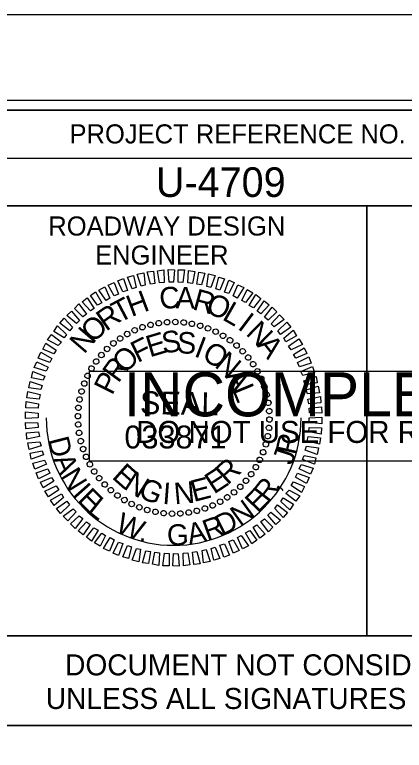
# Model space of a CAD drawing. Extents: x 1779926 to 1781626, y 618464 to 619564.
# Drawn here: x 1781400.8 to 1781502.8, y 619371.7 to 619564.2 of the extents above; entities that cross this region are included whole.
import ezdxf

# ---------------------------------------------------------------- set-up
doc = ezdxf.new("R2010")
doc.units = 0
for name, color, linetype in [('Old_Level_58', 7, 'Continuous'), ('Scratch_Level_0', 7, 'Continuous'), ('Sheet Data Field CELL', 7, 'Continuous'), ('Sheet Plot Border Inside CELL', 7, 'Continuous'), ('Sheet Plot Border Outside CELL', 7, 'Continuous'), ('Sheet Professional Seal CELL', 7, 'Continuous'), ('Sheet Profile CELL', 7, 'Continuous'), ('Sheet Profile Grid Major CELL', 7, 'Continuous'), ('Sheet Profile Grid Minor CELL', 7, 'Continuous'), ('Sheet Sticker Exception Certification CELL', 7, 'Continuous'), ('Sheet Sticker Incomplete CELL', 7, 'Continuous')]:
    doc.layers.add(name, color=color, linetype=linetype)

msp = doc.modelspace()

# ---------------------------------------------------------------- linework, layer by layer
at = {"layer": 'Old_Level_58'}
for points in [[(1781392.9, 619378.14), (1781592.96, 619378.14), (1781592.96, 619314.19), (1781392.9, 619314.19)], [(1781392.96, 619378.14), (1781592.96, 619378.14), (1781592.96, 619314.19), (1781392.96, 619314.19)]]:
    msp.add_lwpolyline(points, close=True, dxfattribs=at)
at = {"layer": 'Scratch_Level_0'}
msp.add_arc((1781442.39, 619458.69), 33.36, 180, 360, dxfattribs=at)
at = {"layer": 'Sheet Plot Border Inside CELL'}
msp.add_lwpolyline([(1779938.96, 618486.64), (1781605.46, 618486.64), (1781605.46, 619541.74), (1779938.96, 619541.74)], close=True, dxfattribs=at)
at = {"layer": 'Sheet Plot Border Outside CELL'}
msp.add_lwpolyline([(1779925.96, 618464.19), (1781625.96, 618464.19), (1781625.96, 619564.19), (1779925.96, 619564.19)], close=True, dxfattribs=at)
at = {"layer": 'Sheet Professional Seal CELL'}
for p, q in [((1781434.19, 619482.44), (1781434.19, 619482.44)), ((1781436.29, 619483.04), (1781436.29, 619483.04)), ((1781438.49, 619483.44), (1781438.49, 619483.44)), ((1781440.64, 619483.74), (1781440.64, 619483.74)), ((1781442.84, 619483.79), (1781442.84, 619483.79)), ((1781445.04, 619483.64), (1781445.04, 619483.64)), ((1781447.19, 619483.29), (1781447.19, 619483.29)), ((1781449.29, 619482.84), (1781449.29, 619482.84)), ((1781430.24, 619480.64), (1781430.24, 619480.64)), ((1781432.19, 619481.64), (1781432.19, 619481.64)), ((1781451.39, 619482.14), (1781451.39, 619482.14)), ((1781453.39, 619481.24), (1781453.39, 619481.24)), ((1781428.34, 619479.49), (1781428.34, 619479.49)), ((1781455.34, 619480.24), (1781455.34, 619480.24)), ((1781457.14, 619478.99), (1781457.14, 619478.99)), ((1781424.94, 619476.74), (1781424.94, 619476.74)), ((1781426.59, 619478.24), (1781426.59, 619478.24)), ((1781458.89, 619477.64), (1781458.89, 619477.64)), ((1781423.44, 619475.19), (1781423.44, 619475.19)), ((1781460.44, 619476.14), (1781460.44, 619476.14)), ((1781422.09, 619473.44), (1781422.09, 619473.44)), ((1781461.94, 619474.49), (1781461.94, 619474.49)), ((1781463.19, 619472.74), (1781463.19, 619472.74)), ((1781420.84, 619471.64), (1781420.84, 619471.64)), ((1781464.34, 619470.84), (1781464.34, 619470.84)), ((1781419.84, 619469.69), (1781419.84, 619469.69)), ((1781465.34, 619468.89), (1781465.34, 619468.89)), ((1781418.94, 619467.69), (1781418.94, 619467.69)), ((1781418.24, 619465.59), (1781418.24, 619465.59)), ((1781466.14, 619466.89), (1781466.14, 619466.89)), ((1781417.79, 619463.49), (1781417.79, 619463.49)), ((1781466.74, 619464.79), (1781466.74, 619464.79)), ((1781417.44, 619461.34), (1781417.44, 619461.34)), ((1781467.14, 619462.59), (1781467.14, 619462.59)), ((1781467.44, 619460.44), (1781467.44, 619460.44)), ((1781417.29, 619459.14), (1781417.29, 619459.14)), ((1781442.39, 619458.69), (1781442.39, 619458.69)), ((1781467.49, 619458.24), (1781467.49, 619458.24)), ((1781417.34, 619456.94), (1781417.34, 619456.94)), ((1781467.34, 619456.04), (1781467.34, 619456.04)), ((1781417.64, 619454.79), (1781417.64, 619454.79)), ((1781466.99, 619453.89), (1781466.99, 619453.89)), ((1781418.04, 619452.59), (1781418.04, 619452.59)), ((1781466.54, 619451.79), (1781466.54, 619451.79)), ((1781418.64, 619450.49), (1781418.64, 619450.49)), ((1781465.84, 619449.69), (1781465.84, 619449.69)), ((1781419.44, 619448.49), (1781419.44, 619448.49)), ((1781464.94, 619447.69), (1781464.94, 619447.69)), ((1781420.44, 619446.54), (1781420.44, 619446.54)), ((1781421.59, 619444.64), (1781421.59, 619444.64)), ((1781462.69, 619443.94), (1781462.69, 619443.94)), ((1781463.94, 619445.74), (1781463.94, 619445.74)), ((1781422.84, 619442.89), (1781422.84, 619442.89)), ((1781461.34, 619442.19), (1781461.34, 619442.19)), ((1781424.34, 619441.24), (1781424.34, 619441.24)), ((1781459.84, 619440.64), (1781459.84, 619440.64)), ((1781425.89, 619439.74), (1781425.89, 619439.74)), ((1781427.64, 619438.39), (1781427.64, 619438.39)), ((1781458.19, 619439.14), (1781458.19, 619439.14)), ((1781429.44, 619437.14), (1781429.44, 619437.14)), ((1781431.39, 619436.14), (1781431.39, 619436.14)), ((1781454.54, 619436.74), (1781454.54, 619436.74)), ((1781456.44, 619437.89), (1781456.44, 619437.89)), ((1781433.39, 619435.24), (1781433.39, 619435.24)), ((1781435.49, 619434.54), (1781435.49, 619434.54)), ((1781448.49, 619434.34), (1781448.49, 619434.34)), ((1781450.59, 619434.94), (1781450.59, 619434.94)), ((1781452.59, 619435.74), (1781452.59, 619435.74)), ((1781437.59, 619434.09), (1781437.59, 619434.09)), ((1781439.74, 619433.74), (1781439.74, 619433.74)), ((1781441.94, 619433.59), (1781441.94, 619433.59)), ((1781444.14, 619433.64), (1781444.14, 619433.64)), ((1781446.29, 619433.94), (1781446.29, 619433.94))]:
    msp.add_line(p, q, dxfattribs=at)
for points in [[(1781431.49, 619492.49), (1781430.34, 619495.49), (1781431.89, 619495.94), (1781432.54, 619492.84)], [(1781433.89, 619493.14), (1781432.84, 619496.29), (1781434.54, 619496.64), (1781434.94, 619493.39)], [(1781436.29, 619493.69), (1781435.49, 619496.89), (1781437.14, 619497.04), (1781437.49, 619493.84)], [(1781438.69, 619493.99), (1781438.14, 619497.19), (1781439.84, 619497.39), (1781439.89, 619494.14)], [(1781441.19, 619494.24), (1781440.94, 619497.49), (1781442.59, 619497.44), (1781442.39, 619494.19)], [(1781443.59, 619494.19), (1781443.59, 619497.44), (1781445.24, 619497.39), (1781444.79, 619494.14)], [(1781446.09, 619494.04), (1781446.29, 619497.29), (1781447.94, 619496.99), (1781447.29, 619493.84)], [(1781448.49, 619493.64), (1781448.94, 619496.84), (1781450.59, 619496.59), (1781449.69, 619493.49)], [(1781451.04, 619493.09), (1781451.54, 619496.34), (1781453.24, 619495.94), (1781452.09, 619492.84)], [(1781426.84, 619490.64), (1781425.24, 619493.44), (1781426.79, 619494.14), (1781427.94, 619491.09)], [(1781429.04, 619491.69), (1781427.74, 619494.59), (1781429.24, 619495.19), (1781430.29, 619491.99)], [(1781453.44, 619492.44), (1781454.19, 619495.54), (1781455.74, 619495.04), (1781454.49, 619492.09)], [(1781455.69, 619491.54), (1781456.84, 619494.69), (1781458.24, 619494.09), (1781456.84, 619491.19)], [(1781424.69, 619489.44), (1781422.84, 619492.14), (1781424.39, 619492.94), (1781425.64, 619490.04)], [(1781457.94, 619490.59), (1781459.19, 619493.54), (1781460.74, 619492.84), (1781459.04, 619490.04)], [(1781460.24, 619489.44), (1781461.59, 619492.29), (1781463.09, 619491.44), (1781461.19, 619488.84)], [(1781420.59, 619486.69), (1781418.44, 619489.09), (1781419.79, 619490.14), (1781421.54, 619487.34)], [(1781422.49, 619488.19), (1781420.64, 619490.74), (1781421.94, 619491.69), (1781423.59, 619488.79)], [(1781462.19, 619488.09), (1781463.94, 619490.99), (1781465.24, 619489.94), (1781463.29, 619487.49)], [(1781418.59, 619485.14), (1781416.39, 619487.34), (1781417.59, 619488.54), (1781419.54, 619485.84)], [(1781464.24, 619486.59), (1781466.09, 619489.34), (1781467.39, 619488.24), (1781465.19, 619485.89)], [(1781416.94, 619483.39), (1781414.39, 619485.44), (1781415.64, 619486.59), (1781417.74, 619484.19)], [(1781466.14, 619485.04), (1781468.19, 619487.64), (1781469.39, 619486.44), (1781467.09, 619484.29)], [(1781415.19, 619481.49), (1781412.59, 619483.44), (1781413.69, 619484.74), (1781415.89, 619482.39)], [(1781467.94, 619483.29), (1781470.09, 619485.64), (1781471.29, 619484.44), (1781468.69, 619482.49)], [(1781413.69, 619479.59), (1781410.99, 619481.29), (1781411.94, 619482.74), (1781414.34, 619480.54)], [(1781469.69, 619481.49), (1781471.99, 619483.74), (1781473.04, 619482.39), (1781470.39, 619480.49)], [(1781412.19, 619477.59), (1781409.39, 619479.09), (1781410.39, 619480.49), (1781412.99, 619478.49)], [(1781471.19, 619479.54), (1781473.64, 619481.64), (1781474.59, 619480.19), (1781471.79, 619478.59)], [(1781472.49, 619477.49), (1781475.14, 619479.39), (1781476.09, 619477.89), (1781473.19, 619476.49)], [(1781410.99, 619475.44), (1781408.14, 619476.69), (1781408.89, 619478.24), (1781411.59, 619476.39)], [(1781473.79, 619475.29), (1781476.59, 619477.04), (1781477.24, 619475.49), (1781474.39, 619474.34)], [(1781409.99, 619473.14), (1781406.89, 619474.29), (1781407.64, 619475.84), (1781410.49, 619474.24)], [(1781474.79, 619473.14), (1781477.74, 619474.64), (1781478.39, 619473.04), (1781475.29, 619472.04)], [(1781408.99, 619470.94), (1781405.89, 619471.84), (1781406.54, 619473.39), (1781409.54, 619471.99)], [(1781408.24, 619468.54), (1781405.14, 619469.19), (1781405.49, 619470.84), (1781408.64, 619469.59)], [(1781475.69, 619470.79), (1781478.74, 619472.09), (1781479.29, 619470.54), (1781476.19, 619469.74)], [(1781476.49, 619468.39), (1781479.69, 619469.54), (1781479.99, 619467.89), (1781476.84, 619467.34)], [(1781407.59, 619466.14), (1781404.49, 619466.54), (1781404.84, 619468.24), (1781407.99, 619467.19)], [(1781477.09, 619465.99), (1781480.24, 619466.94), (1781480.54, 619465.24), (1781477.39, 619464.94)], [(1781407.19, 619463.59), (1781403.99, 619463.89), (1781404.19, 619465.59), (1781407.44, 619464.79)], [(1781477.54, 619463.59), (1781480.79, 619464.29), (1781480.94, 619462.59), (1781477.74, 619462.39)], [(1781406.94, 619461.19), (1781403.69, 619461.29), (1781403.79, 619462.94), (1781407.04, 619462.39)], [(1781477.84, 619461.19), (1781481.09, 619461.59), (1781481.19, 619459.89), (1781477.94, 619459.99)], [(1781406.89, 619458.69), (1781403.64, 619458.54), (1781403.64, 619460.24), (1781406.89, 619459.89)], [(1781406.94, 619456.19), (1781403.69, 619455.79), (1781403.59, 619457.49), (1781406.84, 619457.39)], [(1781477.89, 619458.69), (1781481.14, 619458.84), (1781481.14, 619457.14), (1781477.89, 619457.49)], [(1781477.84, 619456.19), (1781481.09, 619456.09), (1781480.99, 619454.44), (1781477.74, 619454.99)], [(1781407.24, 619453.79), (1781403.99, 619453.09), (1781403.84, 619454.79), (1781407.04, 619454.99)], [(1781477.59, 619453.79), (1781480.79, 619453.49), (1781480.59, 619451.79), (1781477.34, 619452.59)], [(1781407.69, 619451.39), (1781404.54, 619450.44), (1781404.24, 619452.14), (1781407.39, 619452.44)], [(1781408.29, 619448.99), (1781405.09, 619447.84), (1781404.79, 619449.49), (1781407.94, 619450.04)], [(1781477.19, 619451.24), (1781480.29, 619450.84), (1781479.94, 619449.14), (1781476.79, 619450.19)], [(1781476.54, 619448.84), (1781479.64, 619448.19), (1781479.29, 619446.54), (1781476.14, 619447.79)], [(1781409.09, 619446.59), (1781406.04, 619445.29), (1781405.49, 619446.84), (1781408.59, 619447.64)], [(1781475.79, 619446.44), (1781478.89, 619445.54), (1781478.24, 619443.99), (1781475.24, 619445.39)], [(1781409.99, 619444.24), (1781407.04, 619442.74), (1781406.39, 619444.34), (1781409.49, 619445.34)], [(1781474.79, 619444.24), (1781477.89, 619443.09), (1781477.14, 619441.54), (1781474.29, 619443.14)], [(1781410.99, 619442.09), (1781408.19, 619440.34), (1781407.54, 619441.89), (1781410.39, 619443.04)], [(1781473.79, 619441.94), (1781476.64, 619440.69), (1781475.89, 619439.14), (1781473.19, 619440.99)], [(1781412.29, 619439.89), (1781409.64, 619437.99), (1781408.69, 619439.49), (1781411.59, 619440.89)], [(1781413.59, 619437.84), (1781411.14, 619435.74), (1781410.19, 619437.19), (1781412.99, 619438.79)], [(1781472.59, 619439.79), (1781475.39, 619438.29), (1781474.39, 619436.89), (1781471.79, 619438.89)], [(1781415.09, 619435.89), (1781412.79, 619433.64), (1781411.74, 619434.99), (1781414.39, 619436.89)], [(1781471.09, 619437.79), (1781473.79, 619436.09), (1781472.84, 619434.64), (1781470.44, 619436.84)], [(1781416.84, 619434.09), (1781414.69, 619431.74), (1781413.49, 619432.94), (1781416.09, 619434.89)], [(1781469.59, 619435.89), (1781472.19, 619433.94), (1781471.09, 619432.64), (1781468.89, 619434.99)], [(1781418.64, 619432.34), (1781416.59, 619429.74), (1781415.39, 619430.94), (1781417.69, 619433.09)], [(1781467.84, 619433.99), (1781470.39, 619431.94), (1781469.14, 619430.79), (1781467.04, 619433.19)], [(1781420.54, 619430.79), (1781418.69, 619428.04), (1781417.39, 619429.14), (1781419.59, 619431.49)], [(1781464.19, 619430.69), (1781466.34, 619428.29), (1781464.99, 619427.24), (1781463.24, 619430.04)], [(1781466.19, 619432.24), (1781468.39, 619430.04), (1781467.19, 619428.84), (1781465.24, 619431.54)], [(1781422.59, 619429.29), (1781420.84, 619426.39), (1781419.54, 619427.44), (1781421.49, 619429.89)], [(1781424.54, 619427.94), (1781423.19, 619425.09), (1781421.69, 619425.94), (1781423.59, 619428.54)], [(1781462.29, 619429.19), (1781464.14, 619426.64), (1781462.84, 619425.69), (1781461.19, 619428.59)], [(1781426.84, 619426.79), (1781425.59, 619423.84), (1781424.04, 619424.54), (1781425.74, 619427.34)], [(1781457.94, 619426.74), (1781459.54, 619423.94), (1781457.99, 619423.24), (1781456.84, 619426.29)], [(1781460.09, 619427.94), (1781461.94, 619425.24), (1781460.39, 619424.44), (1781459.14, 619427.34)], [(1781429.09, 619425.84), (1781427.94, 619422.69), (1781426.54, 619423.29), (1781427.94, 619426.19)], [(1781431.34, 619424.94), (1781430.59, 619421.84), (1781429.04, 619422.34), (1781430.29, 619425.29)], [(1781453.29, 619424.89), (1781454.44, 619421.89), (1781452.89, 619421.44), (1781452.24, 619424.54)], [(1781455.74, 619425.69), (1781457.04, 619422.79), (1781455.54, 619422.19), (1781454.49, 619425.39)], [(1781433.74, 619424.29), (1781433.24, 619421.04), (1781431.54, 619421.44), (1781432.69, 619424.54)], [(1781436.29, 619423.74), (1781435.84, 619420.54), (1781434.19, 619420.79), (1781435.09, 619423.89)], [(1781438.69, 619423.34), (1781438.49, 619420.09), (1781436.84, 619420.39), (1781437.49, 619423.54)], [(1781441.19, 619423.19), (1781441.19, 619419.94), (1781439.54, 619419.99), (1781439.99, 619423.24)], [(1781443.59, 619423.14), (1781443.84, 619419.89), (1781442.19, 619419.94), (1781442.39, 619423.19)], [(1781446.09, 619423.39), (1781446.64, 619420.19), (1781444.94, 619419.99), (1781444.89, 619423.24)], [(1781448.49, 619423.69), (1781449.29, 619420.49), (1781447.64, 619420.34), (1781447.29, 619423.54)], [(1781450.89, 619424.24), (1781451.94, 619421.09), (1781450.24, 619420.74), (1781449.84, 619423.99)]]:
    msp.add_lwpolyline(points, close=True, dxfattribs=at)
for centre, major_axis in [((1781440.64, 619483.71), (-0.05, 0.718)), ((1781442.83, 619483.76), (0.013, 0.72)), ((1781445.02, 619483.63), (0.075, 0.716)), ((1781432.19, 619481.6), (-0.293, 0.658)), ((1781434.23, 619482.4), (-0.234, 0.681)), ((1781436.33, 619483.02), (-0.174, 0.699)), ((1781438.47, 619483.46), (-0.113, 0.711)), ((1781447.18, 619483.31), (0.137, 0.707)), ((1781449.31, 619482.79), (0.198, 0.692)), ((1781451.38, 619482.1), (0.258, 0.672)), ((1781430.24, 619480.62), (-0.349, 0.63)), ((1781453.39, 619481.23), (0.316, 0.647)), ((1781455.31, 619480.18), (0.371, 0.617)), ((1781426.61, 619478.18), (-0.453, 0.56)), ((1781428.37, 619479.48), (-0.403, 0.597)), ((1781457.14, 619478.98), (0.423, 0.582)), ((1781424.97, 619476.73), (-0.5, 0.518)), ((1781458.85, 619477.61), (0.472, 0.543)), ((1781460.44, 619476.11), (0.518, 0.5)), ((1781423.47, 619475.14), (-0.543, 0.472)), ((1781461.88, 619474.47), (0.56, 0.453)), ((1781422.1, 619473.43), (-0.582, 0.423)), ((1781463.19, 619472.71), (0.597, 0.403)), ((1781420.9, 619471.6), (-0.617, 0.371)), ((1781464.33, 619470.85), (0.63, 0.349)), ((1781419.85, 619469.68), (-0.647, 0.316)), ((1781465.31, 619468.89), (0.658, 0.293)), ((1781418.98, 619467.67), (-0.672, 0.258)), ((1781466.11, 619466.85), (0.681, 0.234)), ((1781418.29, 619465.6), (-0.692, 0.198)), ((1781466.73, 619464.75), (0.699, 0.174)), ((1781417.77, 619463.47), (-0.707, 0.137)), ((1781467.17, 619462.61), (0.711, 0.113)), ((1781417.45, 619461.31), (-0.716, 0.075)), ((1781467.41, 619460.44), (0.718, 0.05)), ((1781417.32, 619459.12), (-0.72, 0.013)), ((1781417.38, 619456.94), (-0.718, -0.05)), ((1781467.47, 619458.25), (0.72, -0.013)), ((1781417.62, 619454.76), (-0.711, -0.113)), ((1781467.34, 619456.06), (0.716, -0.075)), ((1781467.01, 619453.9), (0.707, -0.137)), ((1781418.06, 619452.62), (-0.699, -0.174)), ((1781466.5, 619451.77), (0.692, -0.198)), ((1781418.68, 619450.52), (-0.681, -0.234)), ((1781465.81, 619449.7), (0.672, -0.258)), ((1781419.48, 619448.49), (-0.658, -0.293)), ((1781464.94, 619447.69), (0.647, -0.316)), ((1781420.46, 619446.53), (-0.63, -0.349)), ((1781463.89, 619445.77), (0.617, -0.371)), ((1781421.6, 619444.66), (-0.597, -0.403)), ((1781462.68, 619443.94), (0.582, -0.423)), ((1781422.9, 619442.9), (-0.56, -0.453)), ((1781424.35, 619441.26), (-0.518, -0.5)), ((1781461.32, 619442.23), (0.543, -0.472)), ((1781425.94, 619439.76), (-0.472, -0.543)), ((1781458.18, 619439.2), (0.453, -0.56)), ((1781459.82, 619440.65), (0.5, -0.518)), ((1781427.65, 619438.4), (-0.423, -0.582)), ((1781456.42, 619437.89), (0.403, -0.597)), ((1781429.48, 619437.19), (-0.371, -0.617)), ((1781431.4, 619436.14), (-0.316, -0.647)), ((1781452.6, 619435.77), (0.293, -0.658)), ((1781454.55, 619436.75), (0.349, -0.63)), ((1781433.41, 619435.27), (-0.258, -0.672)), ((1781435.48, 619434.58), (-0.198, -0.692)), ((1781437.61, 619434.07), (-0.137, -0.707)), ((1781439.77, 619433.74), (-0.075, -0.716)), ((1781441.96, 619433.61), (-0.013, -0.72)), ((1781444.14, 619433.67), (0.05, -0.718)), ((1781446.32, 619433.91), (0.113, -0.711)), ((1781448.46, 619434.35), (0.174, -0.699)), ((1781450.56, 619434.97), (0.234, -0.681))]:
    msp.add_ellipse(centre, major_axis=major_axis, ratio=0.999708, dxfattribs=at)
at = {"layer": 'Sheet Profile CELL'}
for p, q in [((1781392.91, 619526.64), (1781592.96, 619526.64)), ((1781492.96, 619514.14), (1781492.96, 619401.69))]:
    msp.add_line(p, q, dxfattribs=at)
for points in [[(1781592.96, 619539.19), (1780092.96, 619539.19), (1780092.96, 618489.19), (1781592.96, 618489.19)], [(1781392.91, 619539.19), (1781592.96, 619539.19), (1781592.96, 619514.14), (1781392.91, 619514.14)], [(1781392.91, 619514.14), (1781492.96, 619514.14), (1781492.96, 619401.64), (1781392.91, 619401.64)], [(1781492.96, 619514.14), (1781592.96, 619514.14), (1781592.96, 619401.64), (1781492.96, 619401.64)]]:
    msp.add_lwpolyline(points, close=True, dxfattribs=at)
at = {"layer": 'Sheet Profile Grid Major CELL'}
msp.add_lwpolyline([(1780842.96, 619039.19), (1780892.96, 619039.19), (1780892.96, 619539.19), (1780942.96, 619539.19), (1780942.96, 619039.19), (1780992.96, 619039.19), (1780992.96, 619539.19), (1781042.96, 619539.19), (1781042.96, 619039.19), (1781092.96, 619039.19), (1781092.96, 619539.19), (1781142.96, 619539.19), (1781142.96, 619039.19), (1781192.96, 619039.19), (1781192.96, 619539.19), (1781242.96, 619539.19), (1781242.96, 619039.19), (1781292.96, 619039.19), (1781292.96, 619539.19), (1781342.96, 619539.19), (1781342.96, 619039.19), (1781392.96, 619039.19), (1781392.96, 619539.19), (1781419.26, 619539.19)], dxfattribs=at)
at = {"layer": 'Sheet Sticker Exception Certification CELL'}
for p, q in [((1781392.91, 619401.64), (1781592.95, 619401.64)), ((1781392.91, 619401.64), (1781592.95, 619401.64)), ((1781592.95, 619378.14), (1781392.91, 619378.14)), ((1781592.95, 619378.14), (1781392.91, 619378.14))]:
    msp.add_line(p, q, dxfattribs=at)
at = {"layer": 'Sheet Sticker Incomplete CELL'}
msp.add_lwpolyline([(1781420.37, 619447.38), (1781420.37, 619470.88), (1781567.37, 619470.88), (1781567.37, 619447.38)], close=True, dxfattribs=at)

# ---------------------------------------------------------------- texts
at = {"layer": 'Sheet Data Field CELL'}
msp.add_text('U-4709', height=7.75, dxfattribs=at).set_placement((1781437.72, 619516.5))
at = {"layer": 'Sheet Professional Seal CELL'}
for s, height, rotation, p in [('H', 5.64, 20.6195, (1781431.34, 619485.04)), ('C', 5.64, 6.2199, (1781438.94, 619487.04)), ('A', 5.64, 359.0203, (1781442.89, 619487.34)), ('R', 5.64, 344.6211, (1781447.09, 619487.14)), ('T', 5.64, 27.8198, (1781428.09, 619483.39)), ('O', 5.64, 337.4212, (1781450.44, 619486.39)), ('L', 5.64, 330.2209, (1781454.84, 619484.54)), ('R', 5.64, 35.0205, (1781424.69, 619481.19)), ('I', 5.64, 323.0201, (1781458.89, 619482.14)), ('O', 5.64, 42.2217, (1781421.24, 619478.09)), ('N', 5.64, 49.4235, (1781418.94, 619475.19)), ('N', 5.64, 315.8189, (1781461.04, 619480.59)), ('E', 5.64, 16.6111, (1781436.14, 619474.49)), ('S', 5.64, 7.2556, (1781439.59, 619475.54)), ('S', 5.64, 357.9004, (1781443.19, 619475.59)), ('F', 5.64, 25.967, (1781432.94, 619472.99)), ('I', 5.64, 339.1896, (1781447.49, 619474.89)), ('A', 5.64, 308.6172, (1781463.99, 619477.64)), ('O', 5.64, 44.6812, (1781429.64, 619470.04)), ('O', 5.64, 329.8335, (1781449.49, 619474.19)), ('N', 5.64, 320.4766, (1781452.84, 619472.19)), ('R', 5.64, 54.0397, (1781427.89, 619467.59)), ('P', 5.64, 63.3989, (1781426.29, 619464.39)), ('A', 5.64, 301.7603, (1781455.69, 619469.59)), ('L', 5.64, 292.4008, (1781457.64, 619466.14)), ('SEAL', 5.998, 359, (1781433.54, 619459.69)), ('R', 5.64, 42.4814, (1781456.49, 619440.94)), ('E', 5.64, 318.2769, (1781425.99, 619443.04)), ('E', 5.64, 33.1241, (1781452.94, 619438.59)), ('N', 5.64, 327.634, (1781428.99, 619440.34)), ('G', 5.64, 336.9902, (1781432.79, 619438.09)), ('N', 5.64, 5.0564, (1781442.69, 619436.04)), ('E', 5.64, 14.4118, (1781447.64, 619436.64)), ('I', 5.64, 355.7012, (1781439.34, 619436.19))]:
    msp.add_text(s, height=height, rotation=rotation, dxfattribs=at).set_placement(p)
at = {"layer": 'Sheet Profile CELL'}
for s, height, p in [('PROJECT REFERENCE NO.', 5.0001, (1781415.12, 619530.5)), ('ROADWAY DESIGN', 5.0001, (1781409.57, 619506.4)), ('ENGINEER', 5, (1781421.82, 619498.8))]:
    msp.add_text(s, height=height, dxfattribs=at).set_placement(p)
at = {"layer": 'Sheet Profile Grid Minor CELL'}
msp.add_text('033871', height=5.998, dxfattribs=at).set_placement((1781429.5, 619450.68))
for s, rotation, p in [('D', 284.2682, (1781409.4, 619453.04)), ('R', 77.3541, (1781474.37, 619448.78)), ('.', 84.2805, (1781475.33, 619452.71)), ('J', 72.4855, (1781473.41, 619446.11)), ('A', 293.4128, (1781410.72, 619447.87)), ('N', 301.5986, (1781412.58, 619443.47)), ('R', 52.3788, (1781467.2, 619436.21)), ('I', 311.5304, (1781415.65, 619438.56)), ('E', 315.0508, (1781416.94, 619436.95)), ('E', 45.7958, (1781464.46, 619433.52)), (',', 59.3052, (1781469.72, 619439.37)), ('L', 321.6338, (1781419.6, 619434.18)), ('N', 35.8641, (1781459.78, 619430.09)), ('D', 26.7195, (1781455.02, 619427.69)), ('W', 336.8891, (1781426.85, 619429.04)), ('R', 19.793, (1781451.19, 619426.39)), ('G', 1.6755, (1781440.71, 619425.26)), ('A', 11.6072, (1781446.5, 619425.47)), ('.', 348.4952, (1781433.13, 619426.52))]:
    msp.add_text(s, height=5.5, rotation=rotation, dxfattribs=at).set_placement(p)
at = {"layer": 'Sheet Sticker Exception Certification CELL'}
for s, p in [('DOCUMENT NOT CONSIDERED FINAL', (1781413.98, 619391.3)), ('DOCUMENT NOT CONSIDERED FINAL', (1781413.98, 619391.3)), ('UNLESS ALL SIGNATURES COMPLETED', (1781408.91, 619382.5)), ('UNLESS ALL SIGNATURES COMPLETED', (1781408.91, 619382.5))]:
    msp.add_text(s, height=5.5, dxfattribs=at).set_placement(p)
at = {"layer": 'Sheet Sticker Incomplete CELL'}
for s, height, p in [('INCOMPLETE PLANS', 11.52, (1781429.32, 619459.08)), ('DO NOT USE FOR R/W ACQUISITION', 5.76, (1781432.57, 619452.13))]:
    msp.add_text(s, height=height, dxfattribs=at).set_placement(p)

doc.saveas('drawing.dxf')
